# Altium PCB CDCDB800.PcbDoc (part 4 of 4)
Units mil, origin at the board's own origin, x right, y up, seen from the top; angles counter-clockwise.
Board outline 4100 x 4100 mil, 4 copper layers (Layer 1 - Top Layer, Layer 2 - GND, Layer 3 - PWR, Layer 4 - Bottom Layer), stack 61.2 mil thick; 245 components, 143 nets, 740 pads, 720 vias.
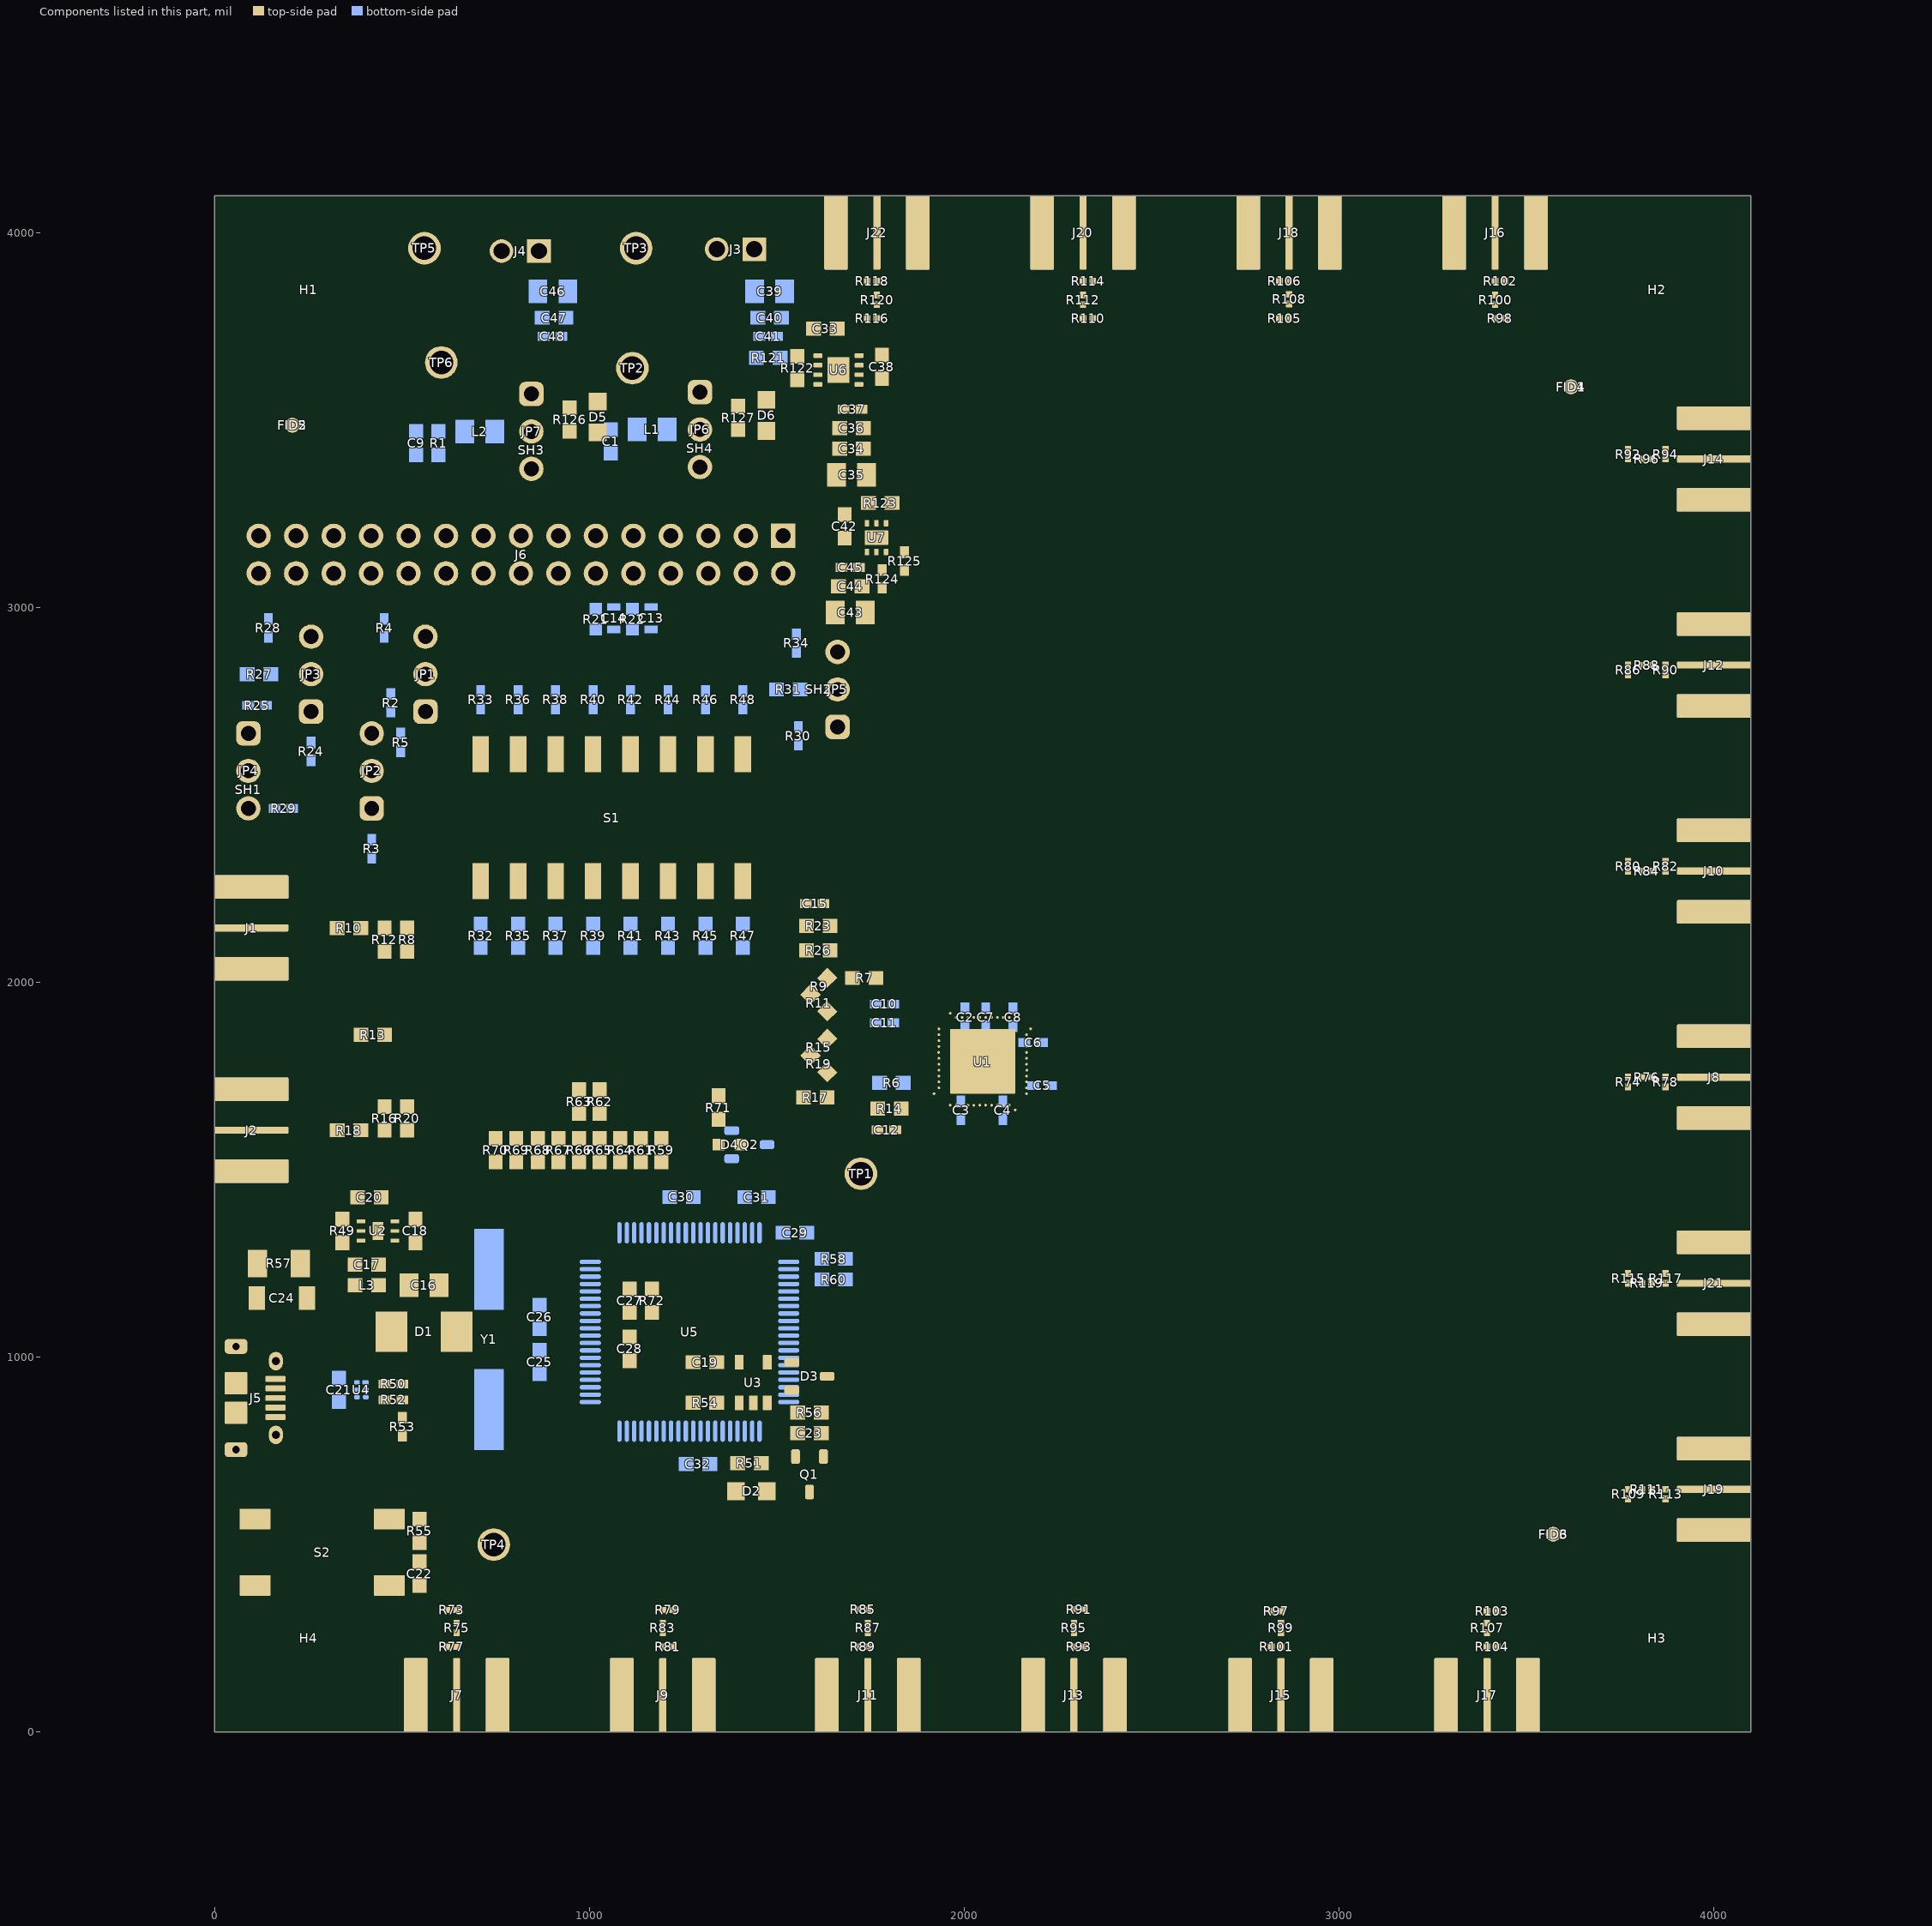
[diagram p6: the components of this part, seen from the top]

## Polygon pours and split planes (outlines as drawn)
GND on Layer 4 - Bottom Layer "Layer 1 - Top Layer-No Net2" (solid, remove dead copper, pour order 1777): 0,0 4100,0 4100,4100 0,4100
VDD on Layer 4 - Bottom Layer "Layer 4 - Bottom Layer-VDD" (solid, remove dead copper, pour order 1776): 1751.4,1547.2 1795.3,1503.3 1795.3,1422.7 1807.2,1410.8 2575.3,1410.8 2611.4,1446.9 2611.4,2926.5 2145.5,3392.4 1222.21,3392.4 1164.8,3449.8 1165,3680 1145,3700 1035,3700 1020,3685 1020,3465 996.4,3441.4 996.4,3277.5 1037.2,3236.7 1547,3236.7 1722.4,3061.3 1722.4,2493.1 2162.9,2052.6 2114.4,2004.1 2007.5,2004.1 1980.6,1977.2 1980.6,1920.4 1990.6,1910.4 2159.3,1910.1 2190.3,1879.1 2190.3,1777.3 2214,1753.6 2214,1685.1 2186.3,1657.4 1977.5,1657.4 1968.1,1648 1968.1,1620.7 1951.2,1603.8 1761.9,1603.8 1751.4,1593.3
VDDR on Layer 4 - Bottom Layer "Layer 4 - Bottom Layer-VDDR" (solid, remove dead copper, pour order 1773): 1494.7,2215.6 1512.8,2233.7 1763,2233.7 1780.3,2216.4 1780.3,1841.8 1763.5,1825 1710,1825 1705,1830 1705,1914.37 1587.47,2031.9 1524.1,2031.9 1494.7,2061.3
GND on Layer 4 - Bottom Layer "Layer 4 - Bottom Layer-GND" (solid, remove dead copper, pour order 1772): 1970.6,1899.8 1970.6,1673 1977.4,1666.2 2187.2,1666.2 2201.7,1680.7 2201.7,1748.8 2191.1,1759.4 2191.1,1761.2 2177.3,1775 2177.3,1882.1 2159.6,1899.8
P3V3 on Layer 4 - Bottom Layer "Layer 4 - Bottom Layer-P3V3" (solid, remove dead copper, pour order 1771): 1175,3515 1175,3435 1185,3425 1350,3425 1355,3430 1355,3510 1345,3520 1180,3520
P3V3_R on Layer 4 - Bottom Layer "Layer 4 - Bottom Layer-P3V3_R" (solid, remove dead copper, pour order 1770): 715,3515 715,3435 725,3425 890,3425 895,3430 895,3510 885,3520 720,3520
VIN2 on Layer 4 - Bottom Layer "Layer 4 - Bottom Layer-VIN2" (solid, remove dead copper, pour order 1774): 715,3530 680,3565 680,3665 625,3720 485,3720 475,3730 475,4055 500,4080 875,4080 900,4055 900,3550 880,3530
VIN1 on Layer 4 - Bottom Layer "Layer 4 - Bottom Layer-VIN1" (solid, remove dead copper, pour order 1775): 1465,4095 1475,4085 1475,3560 1455,3540 1185,3540 1175,3550 1175,3690 1150,3715 1035,3715 1020,3730 1020,4075 1040,4095
GND on Layer 1 - Top Layer "Layer 1 - Top Layer-No Net" (solid, remove dead copper, pour order 1760): 0,0 4100,0 4100,4100 0,4100
U2A_3V3 on Layer 1 - Top Layer "Layer 1 - Top Layer-U2A_3V3" (solid, remove dead copper, pour order 1755): 933,1707.9 933,1726.4 951.3,1744.7 1371.8,1744.7 1387.8,1728.7 1387.8,1686.75 1373.85,1672.8 1325.7,1672.8 1313.1,1660.2 1313.1,1539 1341.5,1510.6 1442.7,1510.6 1488.7,1464.6 1488.7,1383.5 1463.6,1358.4 1266.6,1358.4 1226.1,1398.9 1226.1,1652.1 1189.9,1688.3 952.6,1688.3
VIN2 on Layer 1 - Top Layer "Layer 1 - Top Layer-VIN2" (solid, remove dead copper, pour order 1759): 894.2,3536.4 533,3536.4 486.9,3582.5 486.9,3994.3 541.4,4048.8 883.1,4048.8 919.1,4012.8 919.1,3561.3
VIN1 on Layer 1 - Top Layer "Layer 1 - Top Layer-VIN1" (solid, remove dead copper, pour order 1758): 1336.2,3537.3 1251.3,3537.3 1221.7,3566.9 1221.7,3683.1 1054.1,3850.7 1054.1,4006.9 1076.5,4029.3 1467.1,4029.3 1492.3,4004.1 1492.3,3831 1445.2,3783.9 1445.2,3610.6 1431.8,3597.2 1360.2,3597.2 1345.2,3582.2 1345.2,3546.3
NetC38_1 on Layer 1 - Top Layer "Layer 1 - Top Layer-NetC38_1" (solid, remove dead copper, pour order 1738): 1790.8,3589.6 1802.2,3589.6 ccw(c1802.2,3593.6) 1806.2,3593.6 1806.2,3632.7 ccw(c1801.9,3632.7) 1801.9,3637 1770.9,3637 1753.5,3654.2 1706.6,3654.2 1705.6,3653.2 1705.6,3640 1707.3,3638.3 1743.3,3638.3 1746.6,3635 1746.6,3604.2 1761.2,3589.6
GND on Layer 1 - Top Layer "Layer 1 - Top Layer-GND 2" (solid, remove dead copper, pour order 1740): 1730.4,3166.9 1778.8,3166.9 1782.7,3163 1782.7,3141.6 1795.9,3128.4 1856.7,3128.4 1860.9,3132.6 1860.9,3202.1 1853.1,3209.9 1731.9,3209.9 1729.2,3207.2 1729.2,3168.7
GND on Layer 1 - Top Layer "Layer 1 - Top Layer-GND 3" (solid, remove dead copper, pour order 1747): 1701.9,3206.9 1627.7,3206.9 1617.4,3196.6 1617.4,2963.1 1626.8,2953.7 1680.2,2953.7 1687.8,2961.3 1687.8,3089.6 1690.8,3092.6 1690.8,3147.3 1704.4,3160.9 1704.4,3204.4
GND on Layer 1 - Top Layer "Layer 1 - Top Layer-GND 4" (solid, remove dead copper, pour order 1749): 469.5,1228.2 485.2,1243.9 485.2,1266.4 480.2,1271.4 461.55,1271.4 455.9,1277.05 455.9,1349.3 459,1352.4 504.9,1352.4 512.8,1344.5 555.5,1344.5 563.4,1352.4 563.4,1444.7 553.1,1455 426.8,1455 419.9,1448.1 419.9,1269.1 416.6,1265.8 416.6,1229 417.4,1228.2
GND on Layer 1 - Top Layer "Layer 1 - Top Layer-GND" (solid, remove dead copper, pour order 1746): 1467.48,909.08 1493.5,909 1517.6,884.9 1569.4,884.9 1578.9,875.4 1578.9,720.8 1567.3,709.2 1514.1,709.2 1508.6,714.7 1508.6,765 1482.6,791 1469.9,791 1460.7,800.2 1460.7,902.3
GND on Layer 1 - Top Layer "Layer 1 - Top Layer-GND 1" (solid, remove dead copper, pour order 1753): 1686.3,3544.8 1579.8,3544.8 1550.4,3515.4 1461.4,3515.4 1444.8,3498.8 1444.8,3450.6 1451.8,3443.6 1495.1,3443.6 1621,3317.7 1682.3,3317.7 1689.4,3324.8 1689.4,3509.9 1694.9,3515.4 1694.9,3541.4 1691.8,3544.5
NetC33_1 on Layer 1 - Top Layer "Layer 1 - Top Layer-NetC33_1" (solid, remove dead copper, pour order 1752): 1611.4,3607.3 1590.2,3607.3 1583.54,3613.96 1583.54,3634.5 1580.94,3637.1 1535.4,3637.1 1513.3,3659.2 1513.3,3703 1522.4,3712.1 1610.7,3712.1 1623.4,3724.8 1623.4,3785.3 1605.4,3803.3 1488.5,3803.3 1467.3,3782.1 1467.3,3628.8 1513.5,3582.6 1614.5,3582.6 1622.2,3590.3 1622.2,3604.2 1619.4,3607
0V75 on Layer 1 - Top Layer "Layer 1 - Top Layer-0V75" (solid, remove dead copper, pour order 1751): 1700,3145 1700,2960 1710,2950 1827.6,2950 1842.5,2964.9 1842.5,3062.49 1829.99,3075 1755,3075 1750,3080 1750,3155 1745,3160 1715,3160
5V_USB on Layer 1 - Top Layer "Layer 1 - Top Layer-5V_USB" (solid, remove dead copper, pour order 1754): 400.8,970.8 359.3,929.3 261.8,929.3 257.3,933.8 257.3,1055.1 346.1,1143.9 403.8,1143.9 413.4,1153.5 413.4,1207.7 418.6,1212.9 481.4,1212.9 503.5,1235 545,1235 550,1230 550,984.5 536.3,970.8
NetD2_2 on Layer 1 - Top Layer "Layer 1 - Top Layer-NetD2_2" (solid, remove dead copper, pour order 1742): 1443.54,610.09 1438.54,615.09 1438.54,659.63 1448.99,670.09 1563.54,670.09 1578.54,685.09 1603.54,685.09 1608.54,680.09 1608.54,625.09 1593.54,610.09
NetC23_1 on Layer 1 - Top Layer "Layer 1 - Top Layer-NetC23_1" (solid, remove dead copper, pour order 1748): 1600,975 1595,970 1595,715 1605,705 1655,705 1670,720 1670,965 1660,975
P3V3_R on Layer 1 - Top Layer "Layer 1 - Top Layer-P3V3_R" (solid, remove dead copper, pour order 1743): 815,3515 880,3515 900,3495 965,3495 975,3485 975,3450 955,3430 815,3430 800,3445 800,3500
P3V3 on Layer 1 - Top Layer "Layer 1 - Top Layer-P3V3" (solid, remove dead copper, pour order 1744): 1265,3520 1330,3520 1350,3500 1415,3500 1425,3490 1425,3455 1405,3435 1265,3435 1250,3450 1250,3505
3V3_INT on Layer 1 - Top Layer "Layer 1 - Top Layer-3V3_INT" (solid, remove dead copper, pour order 1757): 1715,3225 1715,3234.3 1725.8,3245.1 1750.5,3245.1 1756.8,3251.8 1770,3265 1770,3555 1750,3575 1736.9,3588.1 1736.9,3603.1 1735,3605 1705,3605 1705,3315 1695,3305 1605,3305 1490,3420 785,3420 765,3400 765,3330 795,3300 1465,3300 1505,3260 1540,3260 1575,3225
USB_GND on Layer 1 - Top Layer "Layer 1 - Top Layer-USB_GND" (solid, remove dead copper, pour order 1756): 165,1290 165,1100 195,1070 195,975 185,965 138.5,965 125.6,952.1 125.6,829.6 135.2,820 180,820 195,805 195,715 185,705 10,705 0,715 0,1295 10,1305 150,1305
U2A_3V3 on Layer 1 - Top Layer "Layer 1 - Top Layer-U2A_3V3 1" (solid, remove dead copper, pour order 1750): 1415,960 1320,960 1310,970 1310,1010 1300,1020 1185,1020 1145,1060 1145,1140 1150,1145 1200,1145 1215,1130 1215,1090 1253.15,1051.85 1388.15,1051.85 1425,1015 1425,970
U2A_3V3 on Layer 1 - Top Layer "Layer 1 - Top Layer-U2A_3V3 2" (solid, remove dead copper, pour order 1739): 472.1,1320 505,1320 515,1330 573.4,1330 583.6,1319.8 583.6,1285.5 578.1,1280 472.4,1280 468.8,1283.6 468.8,1316.7
5V_USB_FILT on Layer 1 - Top Layer "Layer 1 - Top Layer-5V_USB_FILT" (solid, remove dead copper, pour order 1745): 305.4,1330 360,1330 370,1320 399.5,1320 403,1316.5 403,1282.4 400,1279.4 400,1170 390,1160 303.5,1160 295.8,1167.7 295.8,1320.4
NetC20_1 on Layer 1 - Top Layer "Layer 1 - Top Layer-NetC20_1" (solid, remove dead copper, pour order 1741): 315,1345 360,1345 370,1355 401.1,1355 403.5,1357.4 403.5,1444.8 393.3,1455 315,1455 305,1445 305,1355
GND on Layer 3 - PWR "Layer 1 - Top Layer-No Net3" (solid, remove dead copper, pour order 1769): 0,0 4100,0 4100,4100 0,4100
VDD on Layer 3 - PWR "Layer 3 - PWR-VDD" (solid, remove dead copper, pour order 1764): 1971.8,1535.1 2076.7,1535.1 2088.7,1547.1 2088.7,1639.8 2146.6,1697.7 2292.9,1697.7 2302.7,1707.5 2302.7,1940.6 2233.4,2009.9 1921.1,2009.9 1890.6,1979.4 1890.6,1839.7 1821.2,1770.3 1798.3,1770.3 1726.3,1698.3 1726.3,1556.3 1747,1535.6 1819.6,1535.6 1828.9,1544.9 1828.9,1703.2 1838.7,1713 1921.1,1713 1946.3,1687.8 1946.3,1560.6
P3V3 on Layer 3 - PWR "Layer 3 - PWR-P3V3" (solid, remove dead copper, pour order 1767): 1489.2,2506.3 958.2,2506.3 656.9,2205 35,2205 15,2225 15,3195 125,3305 925,3305 1145,3525 1370.7,3525 1586.8,3308.9 1586.8,2603.9
0V75 on Layer 3 - PWR "Layer 3 - PWR-0V75" (solid, remove dead copper, pour order 1768): 507.7,492.7 507.7,537.5 562.1,591.9 818.8,591.9 918,492.7 951.1,492.7 2847.7,492.7 2875,520 3290,520 3439.2,669.2 3439.2,1656.9 3479.4,1696.5 3479.4,2947 3441,2985.4 3441,3394 3384.7,3450.3 3309.1,3525.9 2607.1,3525.9 2502.6,3421.4 2502.6,2942.2 2427.6,2867.2 1803.6,2867.2 1742.8,2928 1742.8,3537 1742.8,3628.3 1615.7,3755.4 1615.7,4100 4060,4100 4100,4060 4100,65 4035,0 507.7,0
GND on Layer 3 - PWR "Layer 3 - PWR-GND 1" (solid, remove dead copper, pour order 1762): 1974.2,1870.6 1974.2,1726 1984.8,1715.4 2115,1715.4 2120.6,1721 2120.6,1861.9 2101.3,1881.2 1983.3,1881.2 1978.3,1876.2
VIN1 on Layer 3 - PWR "Layer 3 - PWR-VIN1" (solid, remove dead copper, pour order 1763): 1454.8,3741.2 1106,3741.2 1037.4,3809.8 1037.4,4014.1 1064.7,4041.4 1478.8,4041.4 1501.1,4019.1 1501.1,3787.5
VIN2 on Layer 3 - PWR "Layer 3 - PWR-VIN2" (solid, remove dead copper, pour order 1765): 894.2,3536.4 533,3536.4 486.9,3582.5 486.9,3994.3 541.4,4048.8 883.1,4048.8 919.1,4012.8 919.1,3561.3
U2A_3V3 on Layer 3 - PWR "Layer 3 - PWR-U2A_3V3" (solid, remove dead copper, pour order 1766): 531.1,1354.2 664.7,1354.2 1214.3,1354.2 1286.5,1426.4 1440.1,1426.4 1555.9,1310.6 1555.9,719.5 1528,691.6 1172.6,691.6 1156.4,707.8 1156.4,902.3 1061.1,997.6 600.6,997.6 500.9,1097.3 500.9,1324
GND on Layer 2 - GND "Layer 1 - Top Layer-No Net1" (solid, remove dead copper, pour order 1761): 0,0 4100,0 4100,4100 0,4100

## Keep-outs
Keep-Out Layer:
  text ".Layer_Name" at -85.4,-1520.9 h60

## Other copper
Layer 1 - Top Layer:
  pour cut-out: 1672.3,2047.7 1672.3,2059.6 1613.2,2059.6 1613.2,2047.7
  region net CK0_P: 882.64,364.99 889.64,364.99 890.84,354.99 884.44,353.09
  region net CK6_N: 3125.17,3733.55 3132.17,3733.55 3133.37,3743.55 3126.97,3745.45
  region net CK7_N: 2006.4,3733.5 2013.4,3733.5 2014.6,3743.5 2008.2,3745.4
  region net CK7_P: 2078.8,3733.5 2071.8,3733.5 2070.6,3743.5 2077,3745.4
  region net CK6_P: 3197.64,3733.55 3190.64,3733.55 3189.44,3743.55 3195.84,3745.45
  region net CK5_P: 3733,3089 3733,3096 3743,3097.2 3744.9,3090.8
  region net CK4_P: 3733,1986.4 3733,1993.4 3743,1994.6 3744.9,1988.2
  region net CK3_P: 3733,883.4 3733,890.4 3743,891.6 3744.9,885.2
  region net CK2_P: 3087.84,362 3094.84,362 3096.04,352 3089.64,350.1
  region net CK1_P: 1982.3,366.99 1989.3,366.99 1990.5,356.99 1984.1,355.09
  region net CK0_N: 953.74,364.99 946.74,364.99 945.54,354.99 951.94,353.09
  region net CK1_N: 2054.71,366.99 2047.71,366.99 2046.51,356.99 2052.91,355.09
  region net CK2_N: 3160.24,362 3153.24,362 3152.04,352 3158.44,350.1
  region net CK3_N: 3733,955.8 3733,948.8 3743,947.6 3744.9,954
  region net CK4_N: 3733,2058.8 3733,2051.8 3743,2050.6 3744.9,2057
  region net CK5_N: 3733,3161.4 3733,3154.4 3743,3153.2 3744.9,3159.6
  region net CK6_P: 2254.83,1917.95 2264.57,1924.16 2268.07,1914.03 2256.54,1909.17
  region net CK6_N: 2251.21,1921.58 2257.42,1931.31 2247.29,1934.82 2242.43,1923.28
  region net CK0_P: 1950.21,1577.99 1940.47,1571.78 1936.97,1581.9 1948.5,1586.76
  region net CK0_N: 1953.83,1574.36 1947.62,1564.63 1957.75,1561.12 1962.61,1572.65
  region net CK1_P: 2015.94,1591.63 2013.45,1580.35 2003.81,1585.03 2008.53,1596.62
  region net CK1_N: 2021.07,1591.63 2023.56,1580.35 2033.2,1585.03 2028.48,1596.62
  region net CK2_P: 2114.67,1574.36 2120.88,1564.63 2110.76,1561.12 2105.9,1572.65
  region net CK2_N: 2118.3,1577.99 2128.03,1571.78 2131.54,1581.9 2120.01,1586.76
  region net CK3_P: 2262.01,1690.21 2268.22,1680.47 2258.1,1676.97 2253.24,1688.5
  region net CK3_N: 2265.64,1693.83 2275.37,1687.62 2278.88,1697.75 2267.35,1702.61
  region net CK5_P: 2378.05,1875.58 2387.78,1881.79 2391.29,1871.66 2379.75,1866.8
  region net CK5_N: 2374.42,1879.21 2380.63,1888.94 2370.5,1892.45 2365.64,1880.91
  region net CK4_P: 2248.37,1755.94 2259.65,1753.45 2254.97,1743.81 2243.38,1748.53
  region net CK4_N: 2248.37,1761.07 2259.65,1763.56 2254.97,1773.2 2243.38,1768.48
  region net CK7_N: 2094.68,1987.96 2092.19,1999.24 2082.55,1994.55 2087.27,1982.96
  region net CK7_P: 2099.81,1987.96 2102.3,1999.24 2111.94,1994.55 2107.22,1982.96
  text "1" at 3484.01,663.34 h60
  text ".Layer_Name" at -85.4,-1520.9 h60
Layer 2 - GND:
  pour cut-out: 0.28,1595.92 1.1,1595.1 197.8,1595.1 199.3,1596.6 199.3,1615.7 197.7,1617.3 1.2,1617.3 0.5,1616.6
  pour cut-out: 0.28,2136.12 1.1,2135.3 197.8,2135.3 199.3,2136.8 199.3,2155.9 197.7,2157.5 1.2,2157.5 0.5,2156.8
  pour cut-out: 656.52,-0.12 657.34,0.7 657.34,197.4 655.84,198.9 636.74,198.9 635.14,197.3 635.14,0.8 635.84,0.1
  pour cut-out: 1206.52,-0.12 1207.34,0.7 1207.34,197.4 1205.84,198.9 1186.74,198.9 1185.14,197.3 1185.14,0.8 1185.84,0.1
  pour cut-out: 1753.99,-0.12 1754.8,0.7 1754.8,197.4 1753.3,198.9 1734.2,198.9 1732.6,197.3 1732.6,0.8 1733.3,0.1
  pour cut-out: 2303.99,-0.12 2304.8,0.7 2304.8,197.4 2303.3,198.9 2284.2,198.9 2282.6,197.3 2282.6,0.8 2283.3,0.1
  pour cut-out: 2856.52,-0.12 2857.34,0.7 2857.34,197.4 2855.84,198.9 2836.74,198.9 2835.14,197.3 2835.14,0.8 2835.84,0.1
  pour cut-out: 3406.52,-0.12 3407.34,0.7 3407.34,197.4 3405.84,198.9 3386.74,198.9 3385.14,197.3 3385.14,0.8 3385.84,0.1
  pour cut-out: 4100.12,658.08 4099.3,658.9 3902.6,658.9 3901.1,657.4 3901.1,638.3 3902.7,636.7 4099.2,636.7 4099.9,637.4
  pour cut-out: 4100.12,1208.08 4099.3,1208.9 3902.6,1208.9 3901.1,1207.4 3901.1,1188.3 3902.7,1186.7 4099.2,1186.7 4099.9,1187.4
  pour cut-out: 4100.12,1758.08 4099.3,1758.9 3902.6,1758.9 3901.1,1757.4 3901.1,1738.3 3902.7,1736.7 4099.2,1736.7 4099.9,1737.4
  pour cut-out: 4100.11,2308.08 4099.3,2308.9 3902.6,2308.9 3901.1,2307.4 3901.1,2288.3 3902.7,2286.7 4099.2,2286.7 4099.9,2287.4
  pour cut-out: 4100.12,2858.08 4099.3,2858.9 3902.6,2858.9 3901.1,2857.4 3901.1,2838.3 3902.7,2836.7 4099.2,2836.7 4099.9,2837.4
  pour cut-out: 4100.12,3408.08 4099.3,3408.9 3902.6,3408.9 3901.1,3407.4 3901.1,3388.3 3902.7,3386.7 4099.2,3386.7 4099.9,3387.4
  pour cut-out: 3407.12,4100.12 3406.3,4099.3 3406.3,3902.6 3407.8,3901.1 3426.9,3901.1 3428.5,3902.7 3428.5,4099.2 3427.8,4099.9
  pour cut-out: 2857.12,4100.12 2856.3,4099.3 2856.3,3902.6 2857.8,3901.1 2876.9,3901.1 2878.5,3902.7 2878.5,4099.2 2877.8,4099.9
  pour cut-out: 2307.12,4100.12 2306.3,4099.3 2306.3,3902.6 2307.8,3901.1 2326.9,3901.1 2328.5,3902.7 2328.5,4099.2 2327.8,4099.9
  pour cut-out: 1757.12,4100.12 1756.3,4099.3 1756.3,3902.6 1757.8,3901.1 1776.9,3901.1 1778.5,3902.7 1778.5,4099.2 1777.8,4099.9
  text "2" at 3484.01,663.34 h60
  text ".Layer_Name" at -85.4,-1520.9 h60
Layer 3 - PWR:
  pour cut-out: 1507.73,2107.53 1561.13,2107.53 1561.13,2063.03 1507.73,2063.03
  pour cut-out: 1667.46,1722.71 1720.86,1722.71 1720.86,1678.21 1667.46,1678.21
  pour cut-out: 2114.79,1485.46 2168.19,1485.46 2168.19,1440.96 2114.79,1440.96
  pour cut-out: 1775.49,1488.74 1828.89,1488.74 1828.89,1444.24 1775.49,1444.24
  pour cut-out: 1775.49,1390.31 1828.89,1390.32 1828.89,1345.81 1775.49,1345.81
  pour cut-out: 2054.56,1398.19 2107.96,1398.19 2107.96,1353.69 2054.56,1353.69
  pour cut-out: 1918.1,1374.57 1971.5,1374.57 1971.5,1330.07 1918.1,1330.07
  pour cut-out: 1918.1,1473 1971.5,1473 1971.5,1428.5 1918.1,1428.5
  pour cut-out: 745,553.96 758.97,552.12 771.98,546.73 783.16,538.16 791.73,526.98 797.12,513.97 798.8,497.1 797.12,486.03 791.73,473.02 783.16,461.84 771.98,453.27 758.97,447.88 745,446.04 731.03,447.88 718.02,453.27 706.84,461.84 698.27,473.02 692.88,486.03 691.04,500 692.88,513.97 698.27,526.98 706.84,538.16 718.02,546.73 731.03,552.12
  pour cut-out: 1686.3,2191.7 1658.4,2191.7 1648.6,2201.5 1648.6,2224.2 1653.5,2229.1 1682.6,2229.1 1690.6,2221.1 1690.6,2205.1
  pour cut-out: 1550.85,2063.2 1522.95,2063.2 1513.15,2073 1513.15,2095.7 1518.05,2100.6 1547.15,2100.6 1555.15,2092.6 1555.15,2076.6
  text "3" at 3484.01,663.34 h60
  text ".Layer_Name" at -85.4,-1520.9 h60
Layer 4 - Bottom Layer:
  pour cut-out: 25.86,725.88 25.86,781.54 94.25,781.54 94.25,725.88
  pour cut-out: 25.87,1001.47 25.86,1057.13 94.25,1057.13 94.25,1001.47
  pour cut-out: 1554.78,3352.07 1554.78,3407.37 1609.68,3407.37 1609.68,3352.07
  pour cut-out: 1772.9,1435.8 1772.9,1491.1 1827.8,1491.1 1827.8,1435.8
  pour cut-out: 2073.48,1389.4 2073.48,1438.67 2128.38,1438.67 2128.38,1389.4
  pour cut-out: 2179.49,1423.47 2234.79,1423.47 2234.79,1368.57 2179.49,1368.57
  pour cut-out: 2354.28,1431.29 2409.58,1431.29 2409.58,1376.39 2354.28,1376.39
  pour cut-out: 2430.57,1429.12 2485.87,1429.12 2485.87,1374.22 2430.57,1374.22
  pour cut-out: 2569.47,1845.22 2624.77,1845.22 2624.77,1790.32 2569.47,1790.32
  pour cut-out: 2576.31,2117.15 2631.61,2117.15 2631.61,2062.25 2576.31,2062.25
  pour cut-out: 2576.31,2215.57 2631.61,2215.57 2631.61,2160.67 2576.31,2160.67
  pour cut-out: 2593.4,2312.5 2648.7,2312.5 2648.7,2257.6 2593.4,2257.6
  pour cut-out: 1622.06,3140.23 1650.66,3111.62 1656.67,3111.62 1664.38,3119.32 1664.38,3124.98 1637.36,3152 1626.02,3140.66 1621.41,3140.66
  text "4" at 3524,663.34 h60
  text ".Layer_Name" at -85.4,-1520.9 h60

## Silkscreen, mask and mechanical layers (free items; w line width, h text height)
Top Overlay:
  circle w6: c1698.9,3136.4 r6.58
  circle w6: c1767.1,3562.5 r6.58
  circle w6: c1396.8,834.8 r6.58
  circle w6: c488.3,1268.7 r6.58
  circle w20: c100.1,627.3 r3.44
  region: 873.9,3637.76 817.3,3637.76 817.3,3623.76 873.9,3623.76
  region: 1323.9,3642.76 1267.3,3642.76 1267.3,3628.76 1323.9,3628.76
  rectangle: 1634.1,2615.65 1690.7,2629.65
  region: 118.5,2731.75 61.9,2731.75 61.9,2717.75 118.5,2717.75
  rectangle: 229.1,2656.5 285.7,2670.5
  rectangle: 390.79,2398.25 447.39,2412.25
  rectangle: 534.1,2656.5 590.7,2670.5
  lines w10: 507.7,1262.6 520.4,1249.9 599.4,1249.9 ; 1754.1,2929.2 1754.1,2880 1791.2,2842.9 ; 1817.6,3046.7 1846.3,3046.7
  text "VIN2" at 504.2,4048.1 h30
  text "VIN1" at 1089.2,4047.3 h30
  text "CK6_P" at 3617,3935.1 h30 r90
  text "CK6_N" at 3068.5,3932.2 h30 r90
  text "CK7_P" at 2519.8,3930.7 h30 r90
  text "CK7_N" at 1963.6,3927.5 h30 r90
  text "VDD" at 1383.2,3771.4 h30
  text "GND" at 1263.7,3767.1 h30
  text "GND" at 706.5,3753.7 h30
  text "VDDR" at 830.2,3754.4 h30
  text "VDD" at 1076,3727.9 h30
  text "GND" at 563.3,3538.5 h30
  text "3V3" at 1415.1,3382.2 h30
  text "3V3_A" at 910.8,3375.1 h30
  text "Power" at 1366.8,3332.9 h30
  text "Power" at 910,3323.2 h30
  text "Indicator" at 1337,3276.8 h30
  text "Indicator" at 910,3268 h30
  text "CK5_N" at 3933.5,3202.7 h30
  text "CK5_P" at 3927.7,2643.4 h30
  text "CK4_N" at 3931.1,2102.5 h30
  text "CK4_P" at 3931.6,1553.3 h30
  text "VDD" at 1627.2,1436.7 h30 r90
  text "CDCDB800 REV A" at 2831.2,1292.4 h60
  text "CK3_N" at 3929.2,1001.5 h30
  text "GND" at 696.7,591.4 h30
  text "CK3_P" at 3918.3,427.2 h30
  text "CK1_P" at 1944.1,46.5 h30 r90
  text "CK1_N" at 2488.3,44.9 h30 r90
  text "CK2_P" at 3042,45.1 h30 r90
  text "CK0_P" at 843.5,43.3 h30 r90
  text "CK0_N" at 1395.2,39.6 h30 r90
  text "CK2_N" at 3591.5,38.4 h30 r90
  text ".Layer_Name" at -85.4,-1520.9 h60
Bottom Overlay:
  lines w6: 432.54,934 cw(c427.1,934) 432.54,934.1
  text ".Layer_Name" at -85.4,-1520.9 h60
Top Paste:
  text ".Layer_Name" at -85.4,-1520.9 h60
Bottom Paste:
  text ".Layer_Name" at -85.4,-1520.9 h60
Top Solder:
  text ".Layer_Name" at -85.4,-1520.9 h60
  text ".Layer_Name" at -85.4,-1520.9 h60
Bottom Solder:
  text ".Layer_Name" at -85.4,-1520.9 h60
Drill Guide:
  text ".Layer_Name" at -85.4,-1520.9 h60
M1 Board Outline:
  the board outline again, w10
  text ".Layer_Name" at -85.4,-1520.9 h60
M2 Board Dimensions:
  rectangle: -537.4,-1062.4 -162.4,-937.4
  rectangle: -662.4,-937.4 -537.4,-812.4
  lines w6: 12.5,-27.24 12.5,-13.1 ; 26.64,-13.1 12.5,-13.1 ; 80.11,-36.97 36.37,-36.97 12.5,-13.1
  lines w7: -662.4,-937.4 337.6,-937.4 ; -537.4,-1062.4 -537.4,-812.4 ; -412.4,-1062.4 -412.4,-812.4 ; -162.4,-1062.4 -162.4,-812.4 ; 87.6,-1062.4 87.6,-812.4 ; -662.4,-1062.4 -662.4,-812.4 337.6,-812.4 337.6,-1062.4 -662.4,-1062.4
  lines w10: 0,0 4100,0 4100,4100 0,4100 0,0
  text "(0,0)" at 93.8,-52.06 h30
M3 3D STEP Top:
  text ".Layer_Name" at -85.4,-1520.9 h60
M4 3D STEP Bottom:
  text ".Layer_Name" at -85.4,-1520.9 h60
M5 Assembly Top:
  lines w10: -954.4,-1592.57 5645.6,-1592.57 ; -954.4,-1389.24 5647.6,-1389.24 ; -954.4,-1185.9 -954.4,-1795.9 3050.6,-1795.9 5647.6,-1795.9 5647.6,-1185.9 -953.9,-1185.9 -953.9,-1795.9 621.6,-1795.9 ; 1510.6,-1795.9 1510.6,-1185.9 ; 2777.6,-1389.24 2777.6,-1185.9 ; 3617.6,-1389.24 3617.6,-1185.9 ; 4239.6,-1802.4 4239.6,-1599.57
  text "COMPONENTS MARKED 'DNP' SHOULD NOT BE POPULATED." at 491.1,-980.9 h60
  text "ASSEMBLY VARIANT:" at 490.6,-1096.4 h60
  text ".VariantName" at 1526.6,-1096.4 h60
  text "PCB VIEWED FROM TOP SIDE" at -890.9,-1318.07 h60
  text "BOARD #:" at 1585.6,-1318.07 h60
  text ".PRJ_title" at 2131.1,-1318.07 h60
  text "REV:" at 2975.6,-1318.07 h60
  text ".PCB_Rev" at 3267.1,-1318.07 h60
  text "SVN REV:" at 3813.6,-1318.07 h60
  text ".VersionControl_RevNumber" at 4319.6,-1318.07 h60
  text "PLOT NAME =" at -890.9,-1726.74 h60
  text ".plot_File_Name" at -85.4,-1726.74 h60
  text "GENERATED    :" at 1587.6,-1726.74 h60
  text ".Print_Date" at 2457.1,-1726.74 h60
  text ".Print_Time" at 3186.1,-1726.74 h60
M6 Assembly Bottom:
  lines w10: -954.9,-1389.74 5647.1,-1389.74 ; -952.9,-1593.07 5647.1,-1593.07 ; 453.1,-1802.9 453.1,-1600.07 ; 1075.1,-1389.74 1075.1,-1186.4 ; 1915.1,-1389.74 1915.1,-1186.4 ; 3182.1,-1796.4 3182.1,-1186.4 ; 4071.1,-1796.4 5646.6,-1796.4 5646.6,-1186.4 -954.9,-1186.4 -954.9,-1796.4 1642.1,-1796.4 5647.1,-1796.4 5647.1,-1186.4
  text "COMPONENTS MARKED 'DNP' SHOULD NOT BE POPULATED." at 5439.6,-980.4 h60
  text ".VariantName" at 4395.6,-1096.4 h60
  text "ASSEMBLY VARIANT:" at 5434.6,-1096.4 h60
  text ".VersionControl_RevNumber" at 373.1,-1318.57 h60
  text "SVN REV:" at 879.1,-1318.57 h60
  text ".PCB_Rev" at 1425.6,-1318.57 h60
  text "REV:" at 1717.1,-1318.57 h60
  text ".PRJ_title" at 2561.6,-1318.57 h60
  text "BOARD #:" at 3107.1,-1318.57 h60
  text "PCB VIEWED FROM BOTTOM SIDE" at 5583.6,-1318.57 h60
  text ".Print_Time" at 1506.6,-1727.24 h60
  text ".Print_Date" at 2235.6,-1727.24 h60
  text "GENERATED    :" at 3105.1,-1727.24 h60
  text ".plot_File_Name" at 4778.1,-1727.24 h60
  text "PLOT NAME =" at 5583.6,-1727.24 h60
M9 Title Sheet:
  lines w10: -1255.4,1653.99 -955.4,1653.99 ; -1255.4,5403.99 -955.4,5403.99 ; -1255.4,9153.99 -955.4,9153.99 ; 2079.6,-2096.01 2079.6,-1796.01 ; 2079.6,12603.99 2079.6,12903.99 ; 5409.6,-2096.01 5409.6,-1796.01 ; 5409.6,12603.99 5409.6,12903.99 ; 8744.6,-2096.01 8744.6,-1796.01 ; 8744.6,12603.99 8744.6,12903.99 ; 10458.1,-1805.01 10458.1,-1195.01 15440.6,-1195.01 ; 12074.6,-2096.01 12074.6,-1796.01 ; 12074.6,12603.99 12074.6,12903.99 ; 15409.6,-2096.01 15409.6,-1796.01 ; 15409.6,12603.99 15409.6,12903.99 ; 15440.6,-1805.01 15440.6,-1195.01 ; 15440.6,-1495.01 18440.6,-1495.01 ; 15440.6,-895.01 18440.6,-895.01 ; 15441.6,-301.01 18441.6,-301.01 ; 16945.6,-1795.01 16945.6,-1195.01 ; 18440.6,-1195.01 15440.6,-1195.01 ; 18440.6,-595.01 15440.6,-595.01 ; 18444.6,1653.99 18744.6,1653.99 ; 18444.6,5403.99 18744.6,5403.99 ; 18444.6,9153.99 18744.6,9153.99 ; 18445.6,199.49 15441.6,199.49 15440.6,199.49 15440.6,-301.01 15440.6,-595.01 ; 15440.6,-1195.01 15440.6,-595.01 ; -1255.4,-2096.01 -1255.4,12903.99 18744.6,12903.99 18744.6,-2096.01 -1255.4,-2096.01 ; -955.4,-1796.01 -955.4,12603.99 18444.6,12603.99 18444.6,-1796.01 -955.4,-1796.01
  text "1" at 395.94,12718.99 h70
  text "2" at 3721.6,12718.99 h70
  text "3" at 7051.6,12718.99 h70
  text "4" at 10386.6,12718.99 h70
  text "5" at 13711.6,12718.99 h70
  text "6" at 17046.6,12718.99 h70
  text "A" at -1125.4,10940.99 h70
  text "A" at 18574.6,10940.99 h70
  text "B" at -1125.4,7190.99 h70
  text "B" at 18574.6,7190.99 h70
  text "C" at -1125.4,3440.99 h70
  text "C" at 18574.6,3440.99 h70
  text "D" at -1125.4,-309.01 h70
  text "D" at 18574.6,-309.01 h70
  text "PROJECT TITLE:" at 15480.6,-394.01 h45
  text ".PRJ_Title" at 15530.6,-527.34 h70
  text "DESIGNED FOR:" at 15480.6,-695.01 h45
  text ".PRJ_Customer" at 15530.6,-835.01 h70
  text "FILE NAME:" at 15480.6,-995.01 h45
  text ".PCB_File_Name_No_Path" at 15530.6,-1115.01 h70
  text "Texas Instruments (TI) and/or its licensors do not warrant the accuracy or completeness of this specification" at 10511.1,-1276.85 h45
  text "ENGINEER:" at 15480.6,-1285.01 h45
  text "LAYOUT BY:" at 16985.6,-1285.01 h45
  text "or any information contained therein. TI and/or its licensors do not warrant that this design will meet" at 10466.11,-1389.52 h45
  text ".PRJ_Engineer" at 15530.6,-1440 h70
  text ".PCB_Layout" at 17434.1,-1441.7 h70
  text "the specifications, will be suitable for your application or fit for any particular purpose, or will operate in" at 10466.11,-1502.18 h45
  text "ALTIUM DESIGNER VERSION:" at 16985.6,-1595.01 h45
  text "an implementation. TI and/or its licensors do not warrant that the design is production worthy. You should" at 10466.11,-1614.85 h45
  text "completely validate and test your design implementation to confirm the system functionality for your application." at 10511.1,-1727.51 h45
  text ".print_Scale" at 15530.6,-1728.34 h70
  text ".Application_BuildNumber" at 17036.1,-1728.34 h70
  text "1" at 395.94,-1981.01 h70
  text "2" at 3721.6,-1981.01 h70
  text "3" at 7051.6,-1981.01 h70
  text "4" at 10386.6,-1981.01 h70
  text "5" at 13711.6,-1981.01 h70
  text "WO:#308707-8705-D" at 16896.42,-1997.84 h70
  text "6" at 16237.4,-2007.9 h70
M10 Fab Notes:
  lines w8: 6419.58,3985.32 9564.58,3985.32 9564.58,4170.32 ; 6419.96,3984.78 6419.96,4169.78 ; 6421.47,4355.48 9564.57,4355.48 ; 6749.57,4170.48 6749.57,4355.48 6749.57,4505.48 ; 6749.57,4629.87 6749.57,4842.71 ; 6749.57,4842.56 6749.57,5055.4 6749.57,5205.4 ; 6749.58,3985.32 6749.58,4170.32 ; 7229.57,4170.48 7229.57,4355.48 7229.57,4505.48 ; 7229.57,4629.28 7229.57,4842.71 ; 7229.57,4841.97 7229.57,5055.4 7229.57,5205.4 ; 7229.58,3985.32 7229.58,4170.32 ; 7569.57,4170.48 7569.57,4360.48 ; 7569.57,4355.48 7569.57,4505.48 ; 7569.58,3985.32 7569.58,4175.32 ; 8171.7,3985.32 8171.7,4175.32 ; 8171.69,4170.48 8171.69,4360.48 ; 8171.69,4355.48 8171.69,4505.48 ; 8179.57,4631.71 8179.57,4847.71 ; 8179.57,4844.4 8179.57,5060.4 ; 8179.57,5055.4 8179.57,5205.4 ; 8829.57,4170.48 8829.57,4355.48 8829.57,4505.48 ; 8829.57,4631.45 8829.57,4842.71 ; 8829.57,4844.14 8829.57,5055.4 8829.57,5205.4 ; 8829.58,3985.32 8829.58,4170.32 ; 6419.57,4842.71 6419.57,4630.02 9564.57,4630.02 9564.57,4842.71 ; 6419.57,4842.71 9564.57,4842.71 ; 6419.57,4842.71 6419.57,5055.4 ; 6419.57,5055.4 9564.57,5055.4 ; 6419.57,5055.4 6419.57,5205.4 9564.57,5205.4 9564.57,5055.4 ; 9564.57,4355.48 9564.57,4505.48 6419.57,4505.48 6419.57,4170.48 9564.57,4170.48 9564.57,4355.48 ; 9564.57,4842.71 9564.57,5055.4 ; 6449.57,5286.92 6534.83,5286.92 6534.83,5387.83 6449.57,5387.83 6449.57,5286.92
  lines w10.1: -49.94,6644.3 529.54,6645.11 ; -48.54,6669.37 526.6,6669.37 ; 16.65,5985.85 -99.86,5985.85 -99.86,6103.03 16.65,6103.03 ; 17.35,5985.85 17.35,6103.03 ; 24.55,5850.05 -91.96,5850.05 -91.96,5967.24 24.55,5967.24 ; 25.25,5850.05 25.25,5967.24 ; 6425.22,5251.26 7353.13,5251.26 ; 6425.22,5267.06 7353.13,5267.06
  text "FAB NOTES:" at -42.81,6693.77 h60
  text "1. BOARD SIZE -  4100MIL x 4100MIL." at -55.34,6493.22 h60
  text "2. VENDOR MAY ADJUST SOLDERMASK WHEREVER SOLDERMASK PADS ARE THE SAME SIZE (1:1) AS PER THE MANUFACTURING CAPABILITIES" at -64.83,6369.36 h60
  text "AND ALL OTHER SOLDER MASK PADS SHALL NOT BE MODIFIED, PROVIDED NO ADJACENT COPPER IS EXPOSED AND NO CONFLICT IS PRODUCED" at 105.94,6253.71 h60
  text "WITH ANY STATED \"VIA TENTING/COVERING\" REQUIREMENTS." at 49.22,6141.65 h60
  text "3. \"10\"MIL VIAS ARE TENTED ON TOP SIDES UNLESS OTHERWISE SOLDERMASK IS OPENED IN GERBER." at -68.06,6012.34 h60
  text "4.  REFER IMPEDANCE TABLE FOR IMPEDANCE CONTROL TRACES ON LAYER 1 (TOP)." at -59.58,5874.45 h60
  text "4" at 6470.74,5305.89 h60
  text "IMPEDANCE TABLE:" at 6582.01,5293.99 h60
  text "COPLANAR GND SPACING" at 7316.81,5115.61 h65
  text "LAYER" at 6439.57,5115.4 h70
  text "TRACE WIDTH" at 6774.57,5115.4 h70
  text "IMPEDANCE +/- 10%" at 8194.57,5115.4 h70
  text "REFERENCE LAYER" at 8898.76,5110.92 h70
  text "12 MILS" at 6878.63,4888.75 h65
  text "NA" at 7510.76,4889.08 h65
  text "42.5 OHM" at 8379.7,4888.75 h65
  text "L2-GND" at 9107.32,4888.75 h65
  text "TOP / LAYER" at 6404.12,4843.51 h60
  text "8.8 MILS" at 6878.63,4676.06 h65
  text "NA" at 7510.76,4676.39 h65
  text "50 OHM" at 8379.7,4676.06 h65
  text "L2-GND" at 9107.32,4676.06 h65
  text "TOP / LAYER" at 6404.12,4630.82 h60
  text "COPLANAR" at 7705.81,4448.36 h65
  text "LAYER" at 6487.37,4421.32 h70
  text "TRACE WIDTH" at 6774.57,4420.48 h70
  text "SPACING" at 7259.57,4420.48 h70
  text "IMPEDANCE +/- 10%" at 8194.57,4420.48 h70
  text "REFERENCE LAYER" at 8919.57,4420.48 h70
  text "SPACING" at 7728.77,4377.55 h65
  text "10 MILS" at 6875.47,4254.74 h65
  text "10 MILS" at 7302.67,4254.74 h65
  text "NA" at 7748.73,4254.73 h65
  text "85 OHM" at 8376.55,4254.74 h65
  text "L2-GND" at 9104.16,4254.74 h65
  text "TOP / LAYER" at 6410.74,4203.13 h70
  text "7.5 MILS" at 6875.48,4069.57 h65
  text "5 MILS" at 7302.68,4069.57 h65
  text "NA" at 7748.74,4069.56 h65
  text "85 OHM" at 8376.56,4069.57 h65
  text "L2-GND" at 9104.17,4069.57 h65
  text "TOP / LAYER" at 6410.75,4017.96 h70
M11 Gerber Information:
  lines w10: -954.4,-1592.57 5645.6,-1592.57 ; -954.4,-1389.24 5647.6,-1389.24 ; -954.4,-1185.9 -954.4,-1795.9 3050.6,-1795.9 5647.6,-1795.9 5647.6,-1185.9 -953.9,-1185.9 -953.9,-1795.9 621.6,-1795.9 ; 1510.6,-1795.9 1510.6,-1185.9 ; 2777.6,-1389.24 2777.6,-1185.9 ; 3617.6,-1389.24 3617.6,-1185.9 ; 4239.6,-1802.4 4239.6,-1599.57
  text "ALL ARTWORK VIEWED FROM TOP SIDE" at -890.9,-1318.07 h60
  text "BOARD #:" at 1585.6,-1318.07 h60
  text ".PRJ_title" at 2131.1,-1318.07 h60
  text "REV:" at 2975.6,-1318.07 h60
  text ".PCB_Rev" at 3267.1,-1318.07 h60
  text "SVN REV:" at 3813.6,-1318.07 h60
  text ".VersionControl_RevNumber" at 4319.6,-1318.07 h60
  text "LAYER NAME =" at -890.9,-1520.9 h60
  text "PLOT NAME =" at -890.9,-1726.74 h60
  text ".plot_File_Name" at -85.4,-1726.74 h60
  text "GENERATED    :" at 1587.6,-1726.74 h60
  text ".Print_Date" at 2457.1,-1726.74 h60
  text ".Print_Time" at 3186.1,-1726.74 h60
M12 Stackup:
  drawing of 297 lines, arcs and shapes, not listed
  text "Layer Stackup :" at 6308.99,3459.21 h60
  text "Layer" at 6326.09,3213.9 h60
  text "Name" at 6736,3213.9 h60
  text "Material" at 8145.59,3213.9 h60
  text "Thickness" at 9005.36,3213.9 h60
  text "Constant" at 9655.19,3213.9 h60
  text "Board Layer Stack" at 10225.05,3213.9 h60
  text "1" at 6326.09,3093.9 h60
  text "Top Overlay" at 6736,3093.9 h60
  text "2" at 6326.09,2973.9 h60
  text "Top Solder" at 6736,2973.9 h60
  text "Solder Resist" at 8145.59,2973.9 h60
  text "0.40mil" at 9005.36,2973.9 h60
  text "3.5" at 9655.19,2973.9 h60
  text "3" at 6326.09,2853.9 h60
  text "Layer 1 - Top Layer" at 6736,2853.9 h60
  text "Copper" at 8145.59,2853.9 h60
  text "2.10mil" at 9005.36,2853.9 h60
  text "4" at 6326.09,2733.9 h60
  text "Dielectric 1" at 6736,2733.9 h60
  text "FR-4 High Tg" at 8145.59,2733.9 h60
  text "5.50mil" at 9005.36,2733.9 h60
  text "4.2" at 9655.19,2733.9 h60
  text "5" at 6326.09,2613.9 h60
  text "Layer 2 - GND" at 6736,2613.9 h60
  text "Copper" at 8145.59,2613.9 h60
  text "1.40mil" at 9005.36,2613.9 h60
  text "6" at 6326.09,2493.9 h60
  text "Dielectric 2" at 6736,2493.9 h60
  text "FR-4 High Tg" at 8145.59,2493.9 h60
  text "43.20mil" at 9005.36,2493.9 h60
  text "4.2" at 9655.19,2493.9 h60
  text "7" at 6326.09,2373.9 h60
  text "Layer 3 - PWR" at 6736,2373.9 h60
  text "Copper" at 8145.59,2373.9 h60
  text "1.40mil" at 9005.36,2373.9 h60
  text "8" at 6326.09,2253.9 h60
  text "Dielectric 3" at 6736,2253.9 h60
  text "FR-4 High Tg" at 8145.59,2253.9 h60
  text "5.50mil" at 9005.36,2253.9 h60
  text "4.2" at 9655.19,2253.9 h60
  text "9" at 6326.09,2133.9 h60
  text "Layer 4 - Bottom Layer" at 6736,2133.9 h60
  text "Copper" at 8145.59,2133.9 h60
  text "2.10mil" at 9005.36,2133.9 h60
  text "10" at 6326.09,2013.9 h60
  text "Bottom Solder" at 6736,2013.9 h60
  text "Solder Resist" at 8145.59,2013.9 h60
  text "0.40mil" at 9005.36,2013.9 h60
  text "3.5" at 9655.19,2013.9 h60
  text "11" at 6326.09,1893.9 h60
  text "Bottom Overlay" at 6736,1893.9 h60
  text "THIS IS AN IMPEDANCE CONTROLLED BOARD" at 7323.37,1725.22 h60
  text "NOTE:" at 6428.06,1700.93 h60
  text "1.CORE AND PREPREG THICKNESSES ARE UP TO FAB SHOP TO SELECT." at 6428.61,1540.4 h60
  text "2.EXTERNAL LAYER CU THICKNESS ARE FINISHED THICKNESS AFTER PLATING." at 6416.57,1365.76 h60
M13 Component Bodies Top:
  text ".Layer_Name" at -85.4,-1520.9 h60
M14 Component Bodies Bottom:
  text ".Layer_Name" at -85.4,-1520.9 h60
M15 Courtyards Top:
  text ".Layer_Name" at -85.4,-1520.9 h60
M16 Courtyards Bottom:
  text ".Layer_Name" at -85.4,-1520.9 h60
Drill Drawing:
  lines w10: 6451.05,-42.4 6451.05,-28.59 6464.86,-14.77 6451.05,-0.96 6451.05,12.85 6464.86,12.85 6478.67,-0.96 6492.49,12.85 6506.3,12.85 6506.3,-0.96 6492.49,-14.77 6506.3,-28.59 6506.3,-42.4 6492.49,-42.4 6478.67,-28.59 6464.86,-42.4 6451.05,-42.4 ; 6451.05,95.73 6464.86,95.73 6464.86,81.92 6492.49,81.92 6492.49,95.73 6506.3,95.73 6506.3,123.36 6492.49,123.36 6492.49,137.17 6464.86,137.17 6464.86,123.36 6451.05,123.36 6451.05,95.73 ; 6451.05,261.49 6506.3,261.49 6478.67,206.24 6451.05,261.49 ; 6451.05,330.56 6451.05,344.37 6464.86,358.19 6451.05,372 6451.05,385.81 6464.86,385.81 6478.67,372 6492.49,385.81 6506.3,385.81 6506.3,372 6492.49,358.19 6506.3,344.37 6506.3,330.56 6492.49,330.56 6478.67,344.37 6464.86,330.56 6451.05,330.56 ; 6451.05,454.88 6506.3,454.88 6506.3,510.13 6451.05,510.13 6451.05,454.88 ; 6451.05,579.2 6478.67,593.01 6506.3,579.2 6492.49,606.83 6506.3,634.45 6478.67,620.64 6451.05,634.45 6464.86,606.83 6451.05,579.2 ; 6451.05,758.77 6506.3,758.77 6478.67,703.52 6451.05,758.77 ; 6462.1,341.61 6462.1,349.9 6470.39,358.19 6462.1,366.47 6462.1,374.76 6470.39,374.76 6478.67,366.47 6486.96,374.76 6495.25,374.76 6495.25,366.47 6486.96,358.19 6495.25,349.9 6495.25,341.61 6486.96,341.61 6478.67,349.9 6470.39,341.61 6462.1,341.61 ; 6462.1,747.72 6495.25,747.72 6478.67,714.57 6462.1,747.72
  lines w10.1: 6363.65,553.15 6247.14,553.15 6247.14,670.34 6363.65,670.34 ; 6364.35,553.15 6364.35,670.34
  lines w15: 6400.96,-79.7 10198.09,-79.7 ; 6400.96,790.54 10198.09,790.54 ; 6738.82,-204.02 6738.82,914.86 ; 7040.18,-204.02 7040.18,914.86 ; 7603.45,-204.02 7603.45,914.86 ; 8280.97,-204.02 8280.97,914.86 ; 8844.24,-204.02 8844.24,914.86 ; 9103.38,-204.02 9103.38,914.86 ; 9478.54,-204.02 9478.54,914.86 ; 6400.96,-204.02 10198.09,-204.02 10198.09,914.86 6400.96,914.86 6400.96,-204.02
  text "DRILL CHART:" at 6398.8,961.9 h60
  text "Symbol" at 6475.55,827.84 h72
  text "Count" at 6776.11,827.84 h72
  text "Hole Size" at 7077.48,827.84 h72
  text "Routed Path Length" at 7640.75,827.84 h72
  text "Hole Length" at 8318.27,827.84 h72
  text "Plated" at 8881.54,827.84 h72
  text "Hole Type" at 9140.68,827.84 h72
  text "Hole Tolerance(MIL)" at 9515.84,827.84 h72
  text "22" at 6776.11,703.52 h60
  text "7.87mil (0.200mm)" at 7077.48,703.52 h60
  text "-" at 7640.75,703.52 h60
  text "-" at 8318.27,703.52 h60
  text "PTH" at 8881.54,703.52 h60
  text "Round" at 9140.68,703.52 h60
  text "+0/-7.87" at 9515.84,703.52 h60
  text "698" at 6776.11,579.2 h60
  text "10.00mil (0.254mm)" at 7077.48,579.2 h60
  text "-" at 7640.75,579.2 h60
  text "-" at 8318.27,579.2 h60
  text "PTH" at 8881.54,579.2 h60
  text "Round" at 9140.68,579.2 h60
  text "+0/-10" at 9515.84,579.2 h60
  text "3" at 6279.52,577.55 h60
  text "51" at 6776.11,454.88 h60
  text "40.00mil (1.016mm)" at 7077.48,454.88 h60
  text "-" at 7640.75,454.88 h60
  text "-" at 8318.27,454.88 h60
  text "PTH" at 8881.54,454.88 h60
  text "Round" at 9140.68,454.88 h60
  text "+/-3" at 9515.84,454.88 h60
  text "4" at 6776.11,330.56 h60
  text "43.31mil (1.100mm)" at 7077.48,330.56 h60
  text "-" at 7640.75,330.56 h60
  text "-" at 8318.27,330.56 h60
  text "PTH" at 8881.54,330.56 h60
  text "Round" at 9140.68,330.56 h60
  text "+/-3" at 9515.84,330.56 h60
  text "6" at 6776.11,206.24 h60
  text "63.00mil (1.600mm)" at 7077.48,206.24 h60
  text "-" at 7640.75,206.24 h60
  text "-" at 8318.27,206.24 h60
  text "PTH" at 8881.54,206.24 h60
  text "Round" at 9140.68,206.24 h60
  text "+/-3" at 9515.84,206.24 h60
  text "2" at 6776.11,81.92 h60
  text "19.69mil (0.500mm)" at 7077.48,81.92 h60
  text "25.59mil (0.650mm)" at 7640.75,81.92 h60
  text "45.28mil (1.150mm)" at 8318.27,81.92 h60
  text "PTH" at 8881.54,81.92 h60
  text "Slot" at 9140.68,81.92 h60
  text "2" at 6776.11,-42.4 h60
  text "21.65mil (0.550mm)" at 7077.48,-42.4 h60
  text "11.81mil (0.300mm)" at 7640.75,-42.4 h60
  text "33.47mil (0.850mm)" at 8318.27,-42.4 h60
  text "PTH" at 8881.54,-42.4 h60
  text "Slot" at 9140.68,-42.4 h60
  text "785 Total" at 6776.11,-166.72 h60
  text "Slot definitions :" at 6475.55,-253.74 h60
  text "Routed Path Length" at 6926.26,-253.74 h60
  text "= Calculated from tool start centre position to tool end centre position." at 7466,-253.74 h60
  text "Hole Length" at 6926.26,-303.47 h60
  text "= Routed Path Length + Tool Size = Slot length as defined in the PCB layout" at 7266.2,-303.47 h60
  text "FAB" at -85.4,-1520.9 h60
M17 Embedded Cavity:
  text ".Layer_Name" at -85.4,-1520.9 h60
M18 Embedded Assembly:
  text ".Layer_Name" at -85.4,-1520.9 h60
M19 Embedded Keepout:
  text ".Layer_Name" at -95.4,-1520.9 h60

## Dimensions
0,0 to 4100,0 on M2 Board Dimensions
0,0 to 0,4100 on M2 Board Dimensions
-662.4,-1062.4 to 337.6,-1062.4 on M2 Board Dimensions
